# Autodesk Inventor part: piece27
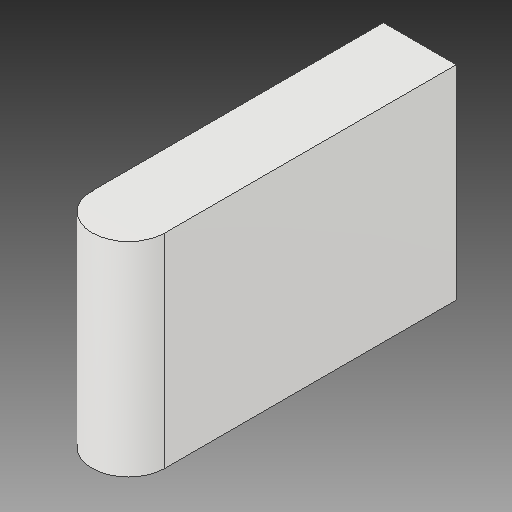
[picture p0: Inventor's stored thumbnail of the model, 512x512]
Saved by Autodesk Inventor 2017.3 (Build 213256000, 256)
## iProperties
Created: 2002-06
Part Number: piece27
Material: Générique
Document SubType Name: Modeling
Designer: ficho
Density: 1 g/cm^3
Appearance: Par défaut
Author: ficho
Sending System: SolidWorks 2009
Last Author: christophe
Last Saved: 2011-02-10
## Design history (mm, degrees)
feature "Base-Extrusion"
node "Solide1"
